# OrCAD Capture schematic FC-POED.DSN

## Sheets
1 INDEX: size A; title: INDEX; rev: 1.1; note: 8000100001
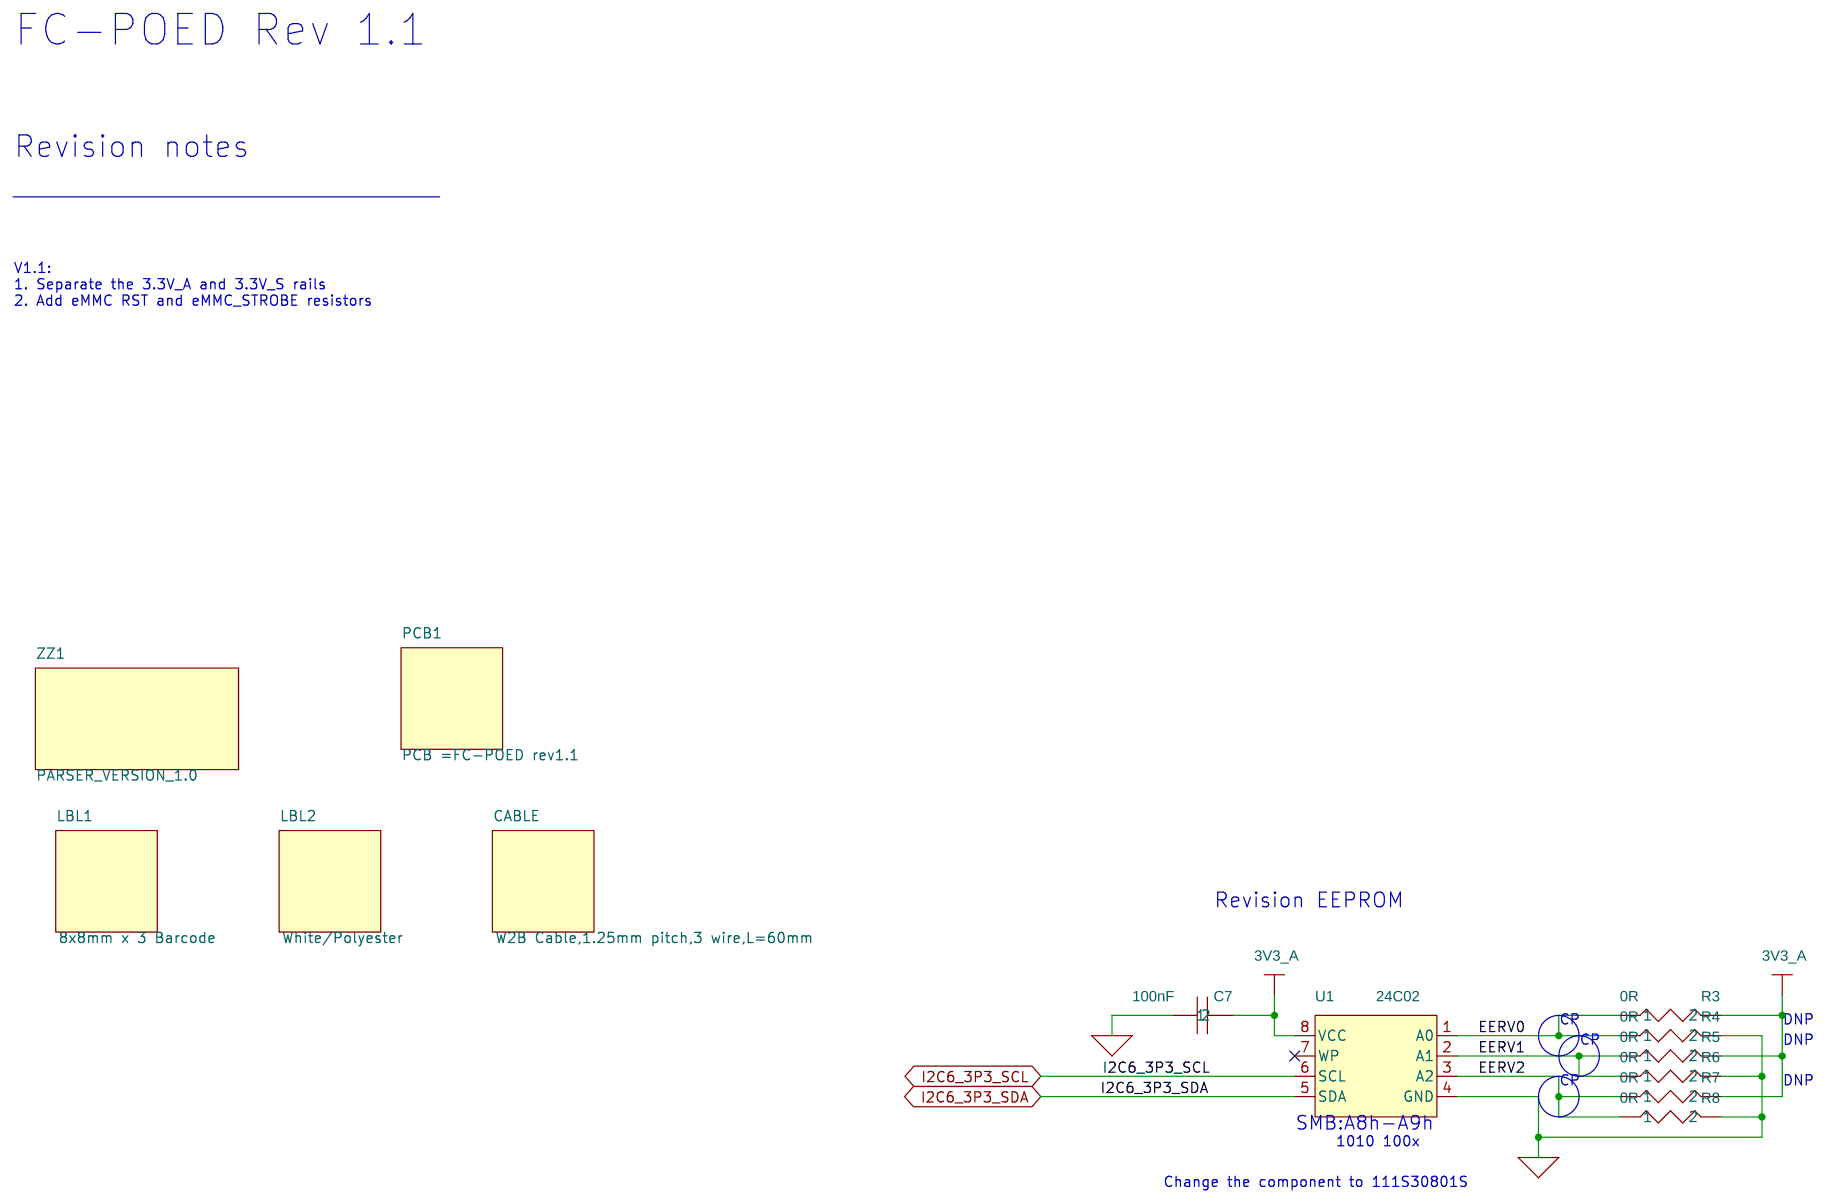
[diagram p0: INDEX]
2 M.2 WiFi: size Custom; title: M.2 interface
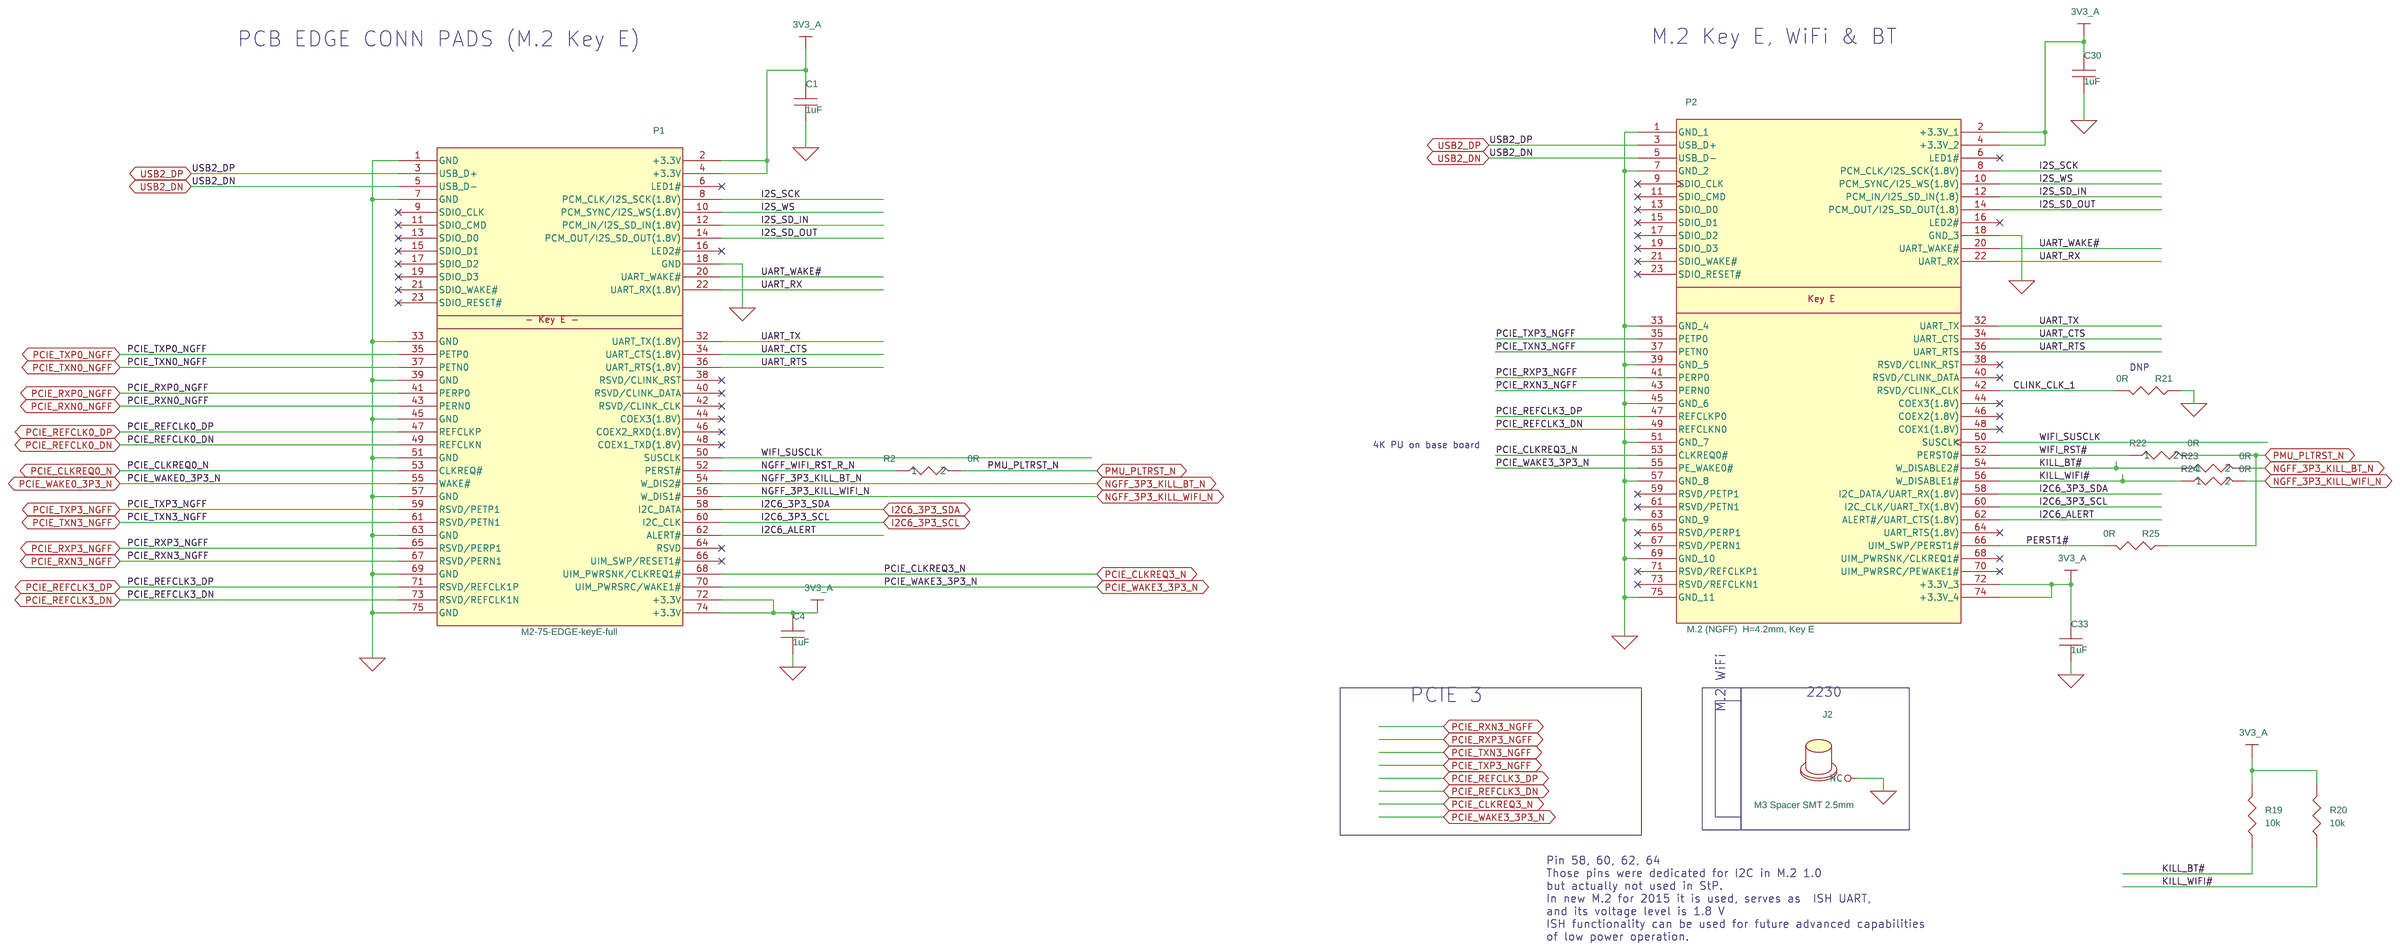
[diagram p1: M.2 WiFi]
3 1Gb LAN: size A3; title: GBE#0
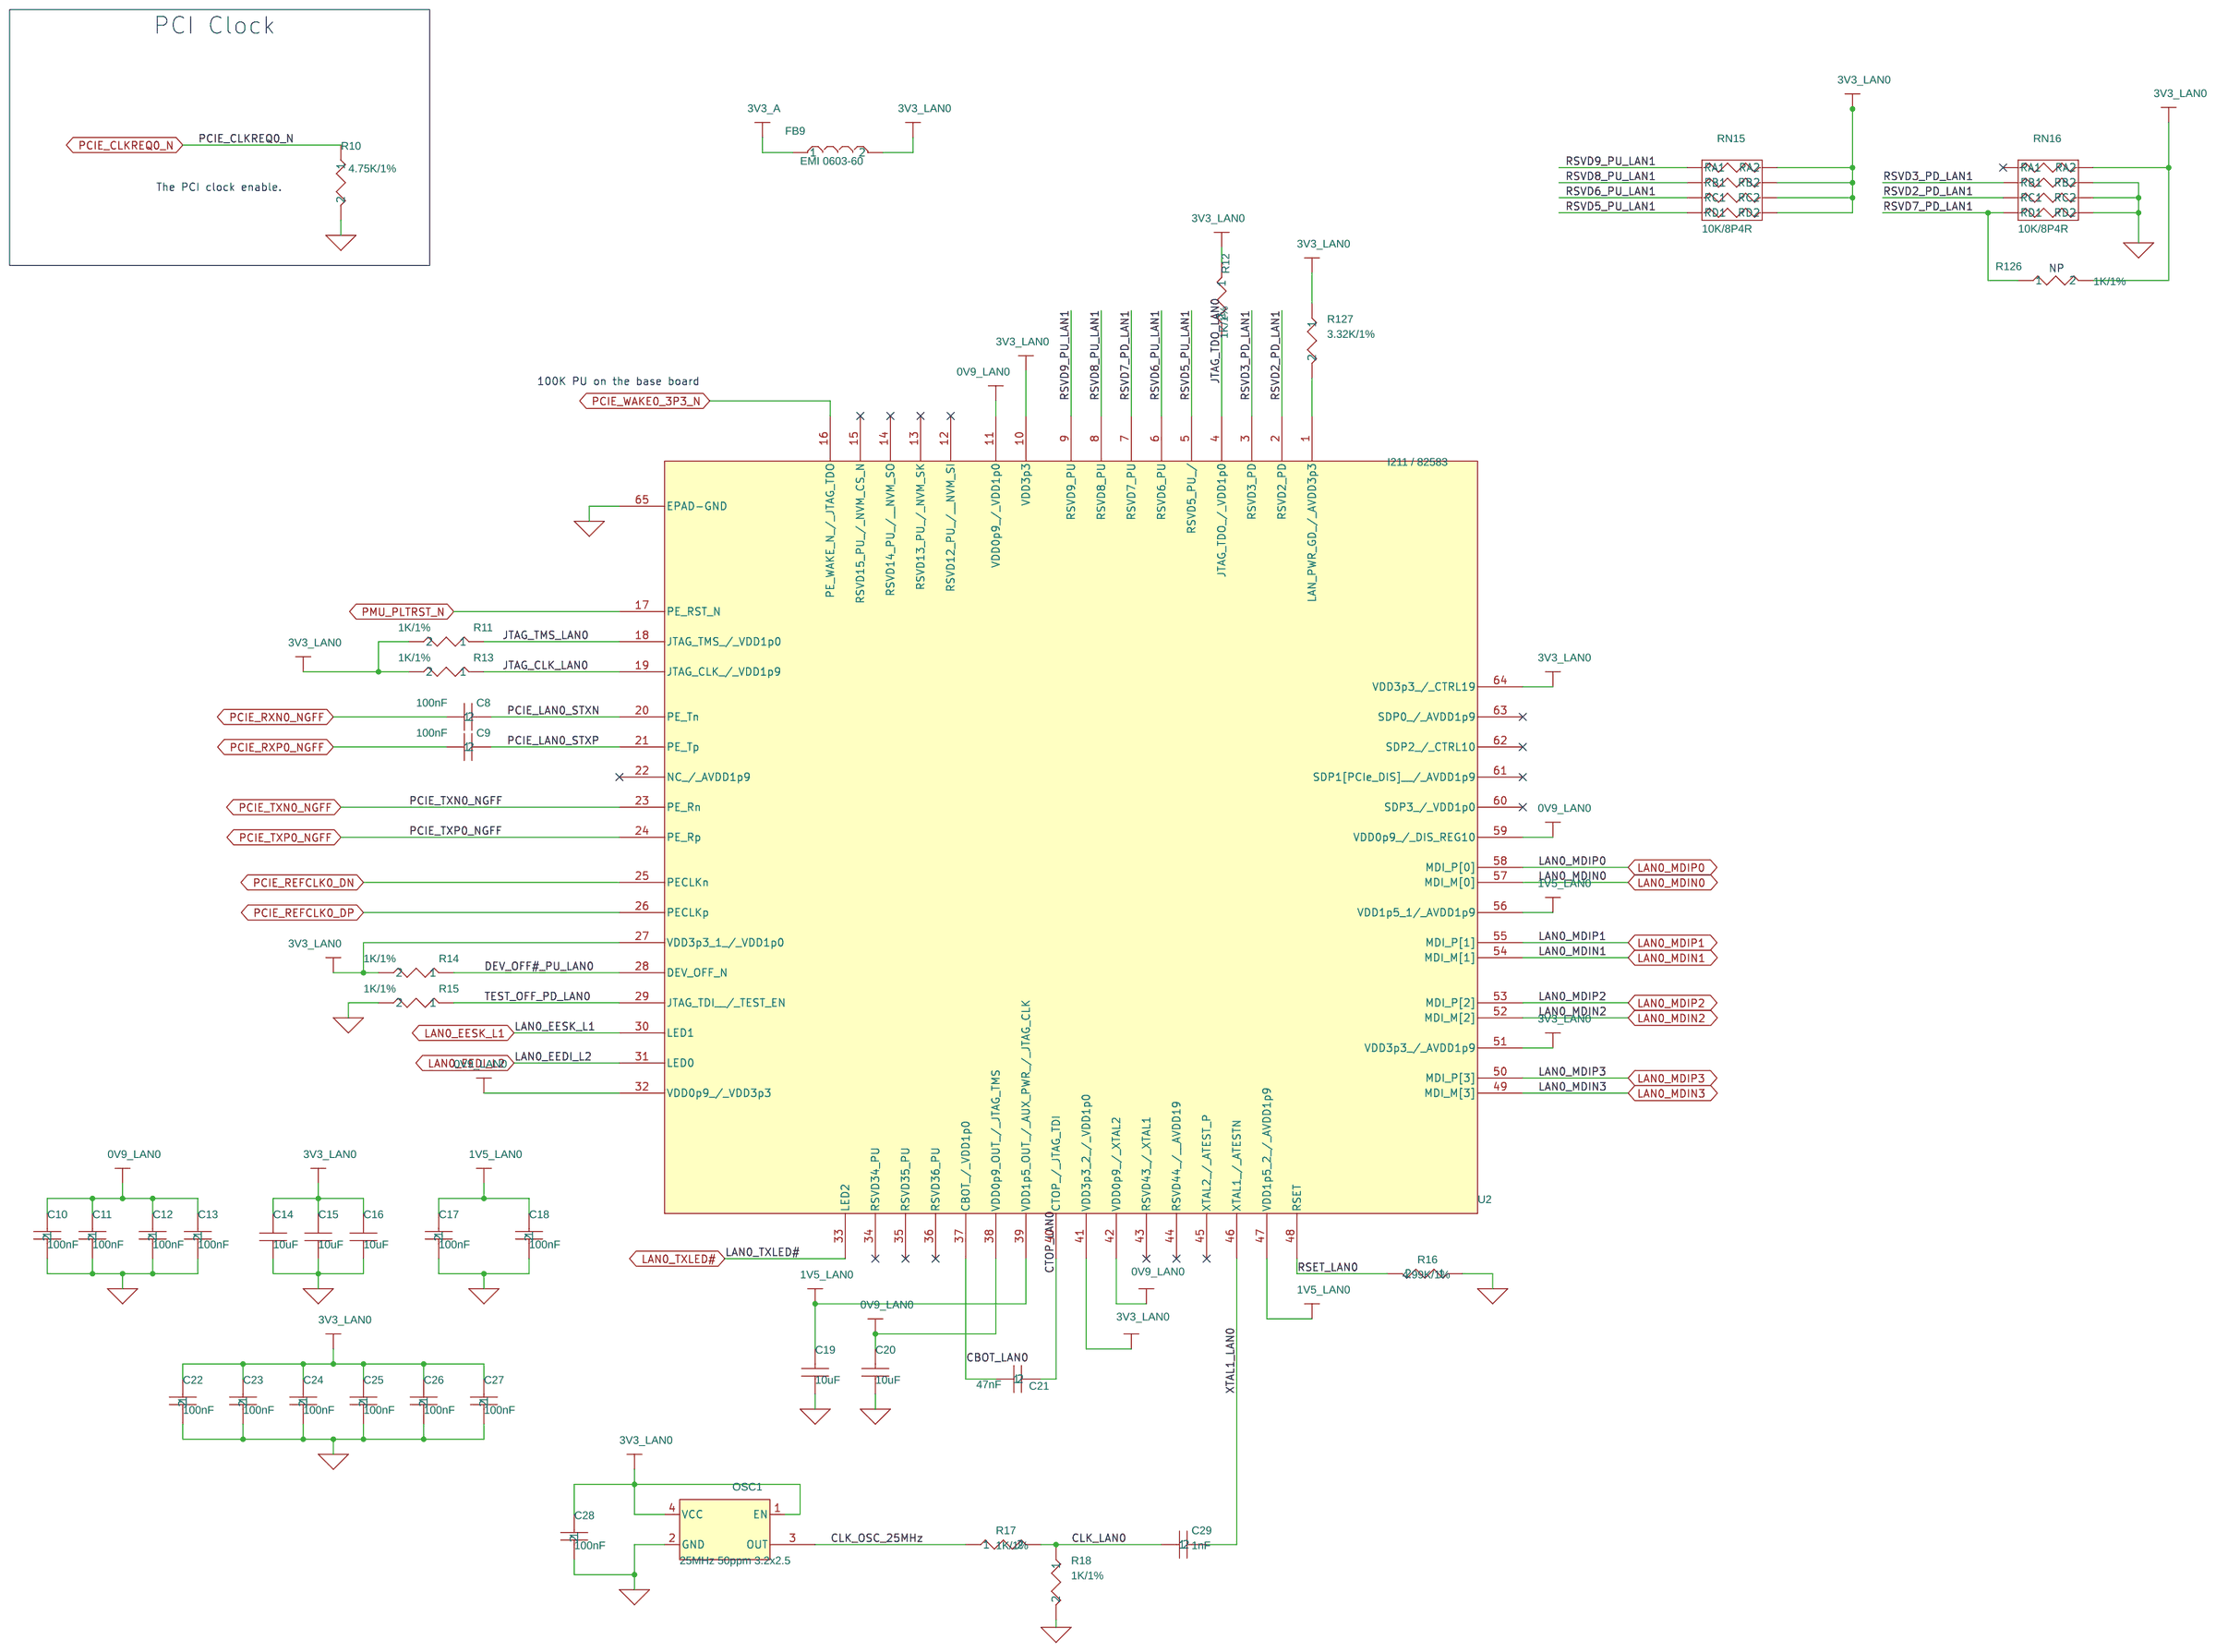
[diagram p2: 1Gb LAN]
4 POE: size C; title: POE
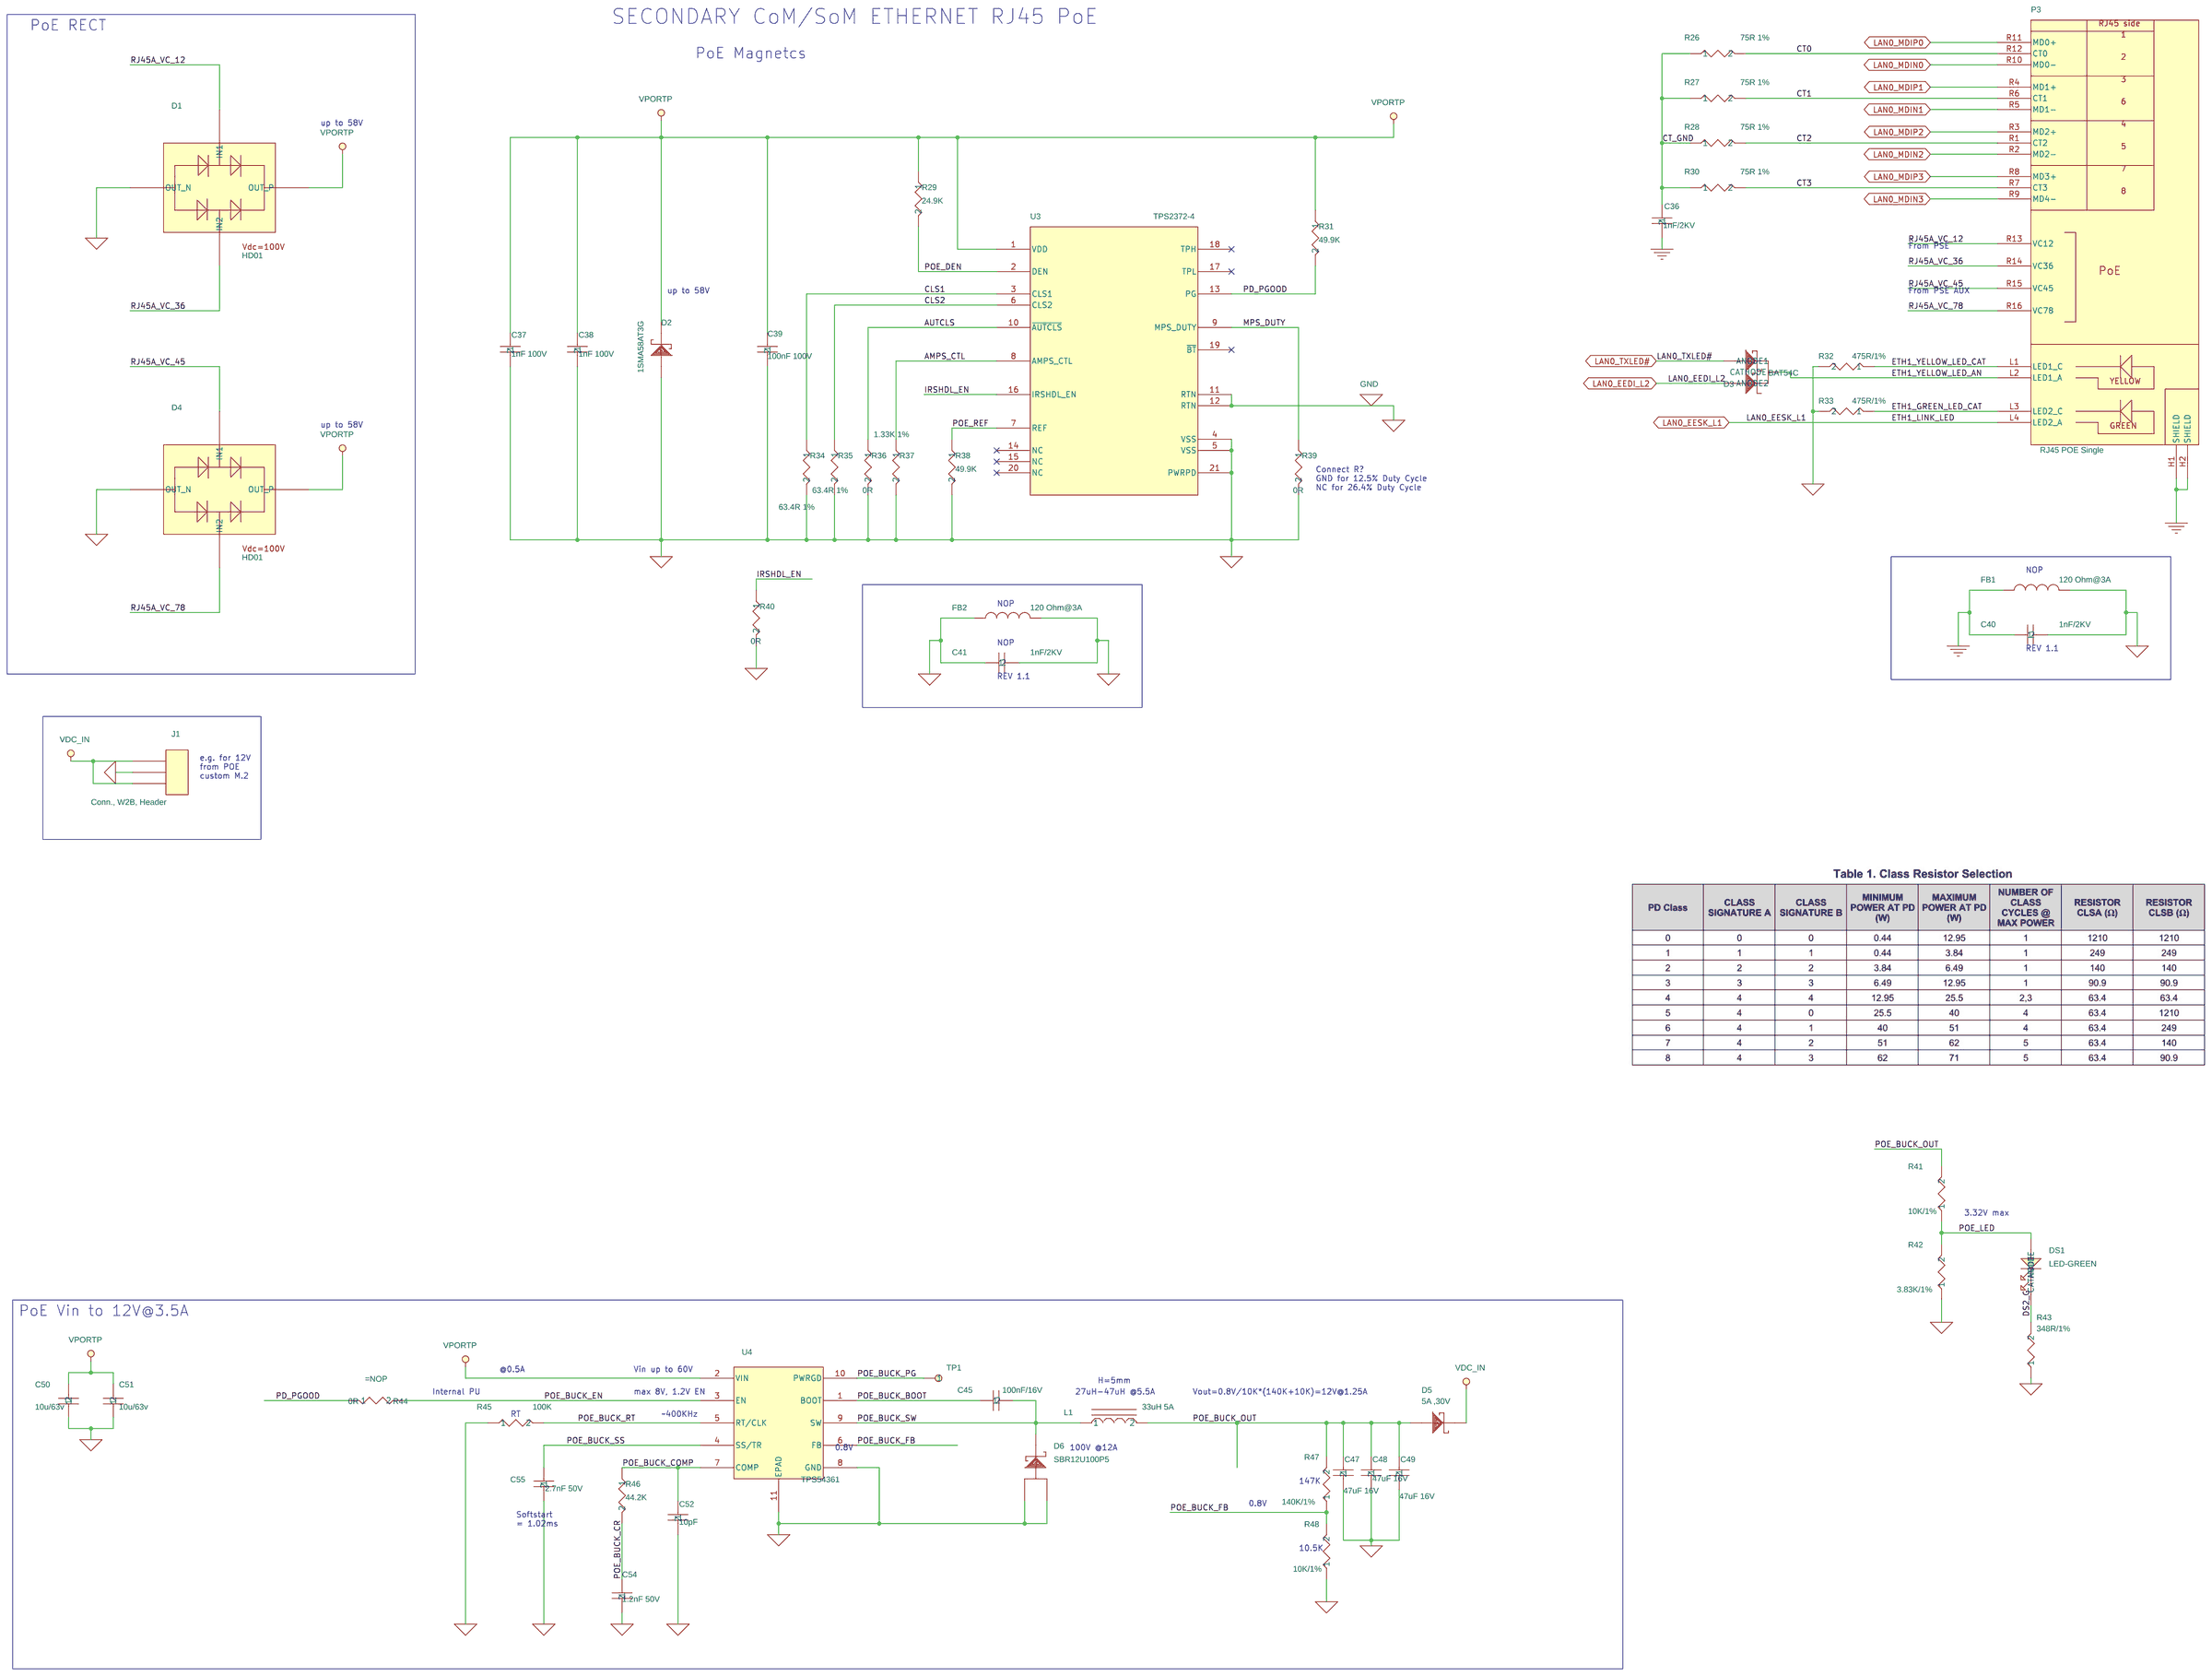
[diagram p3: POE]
5 M.2 SATA: size B; title: M.2 SATA
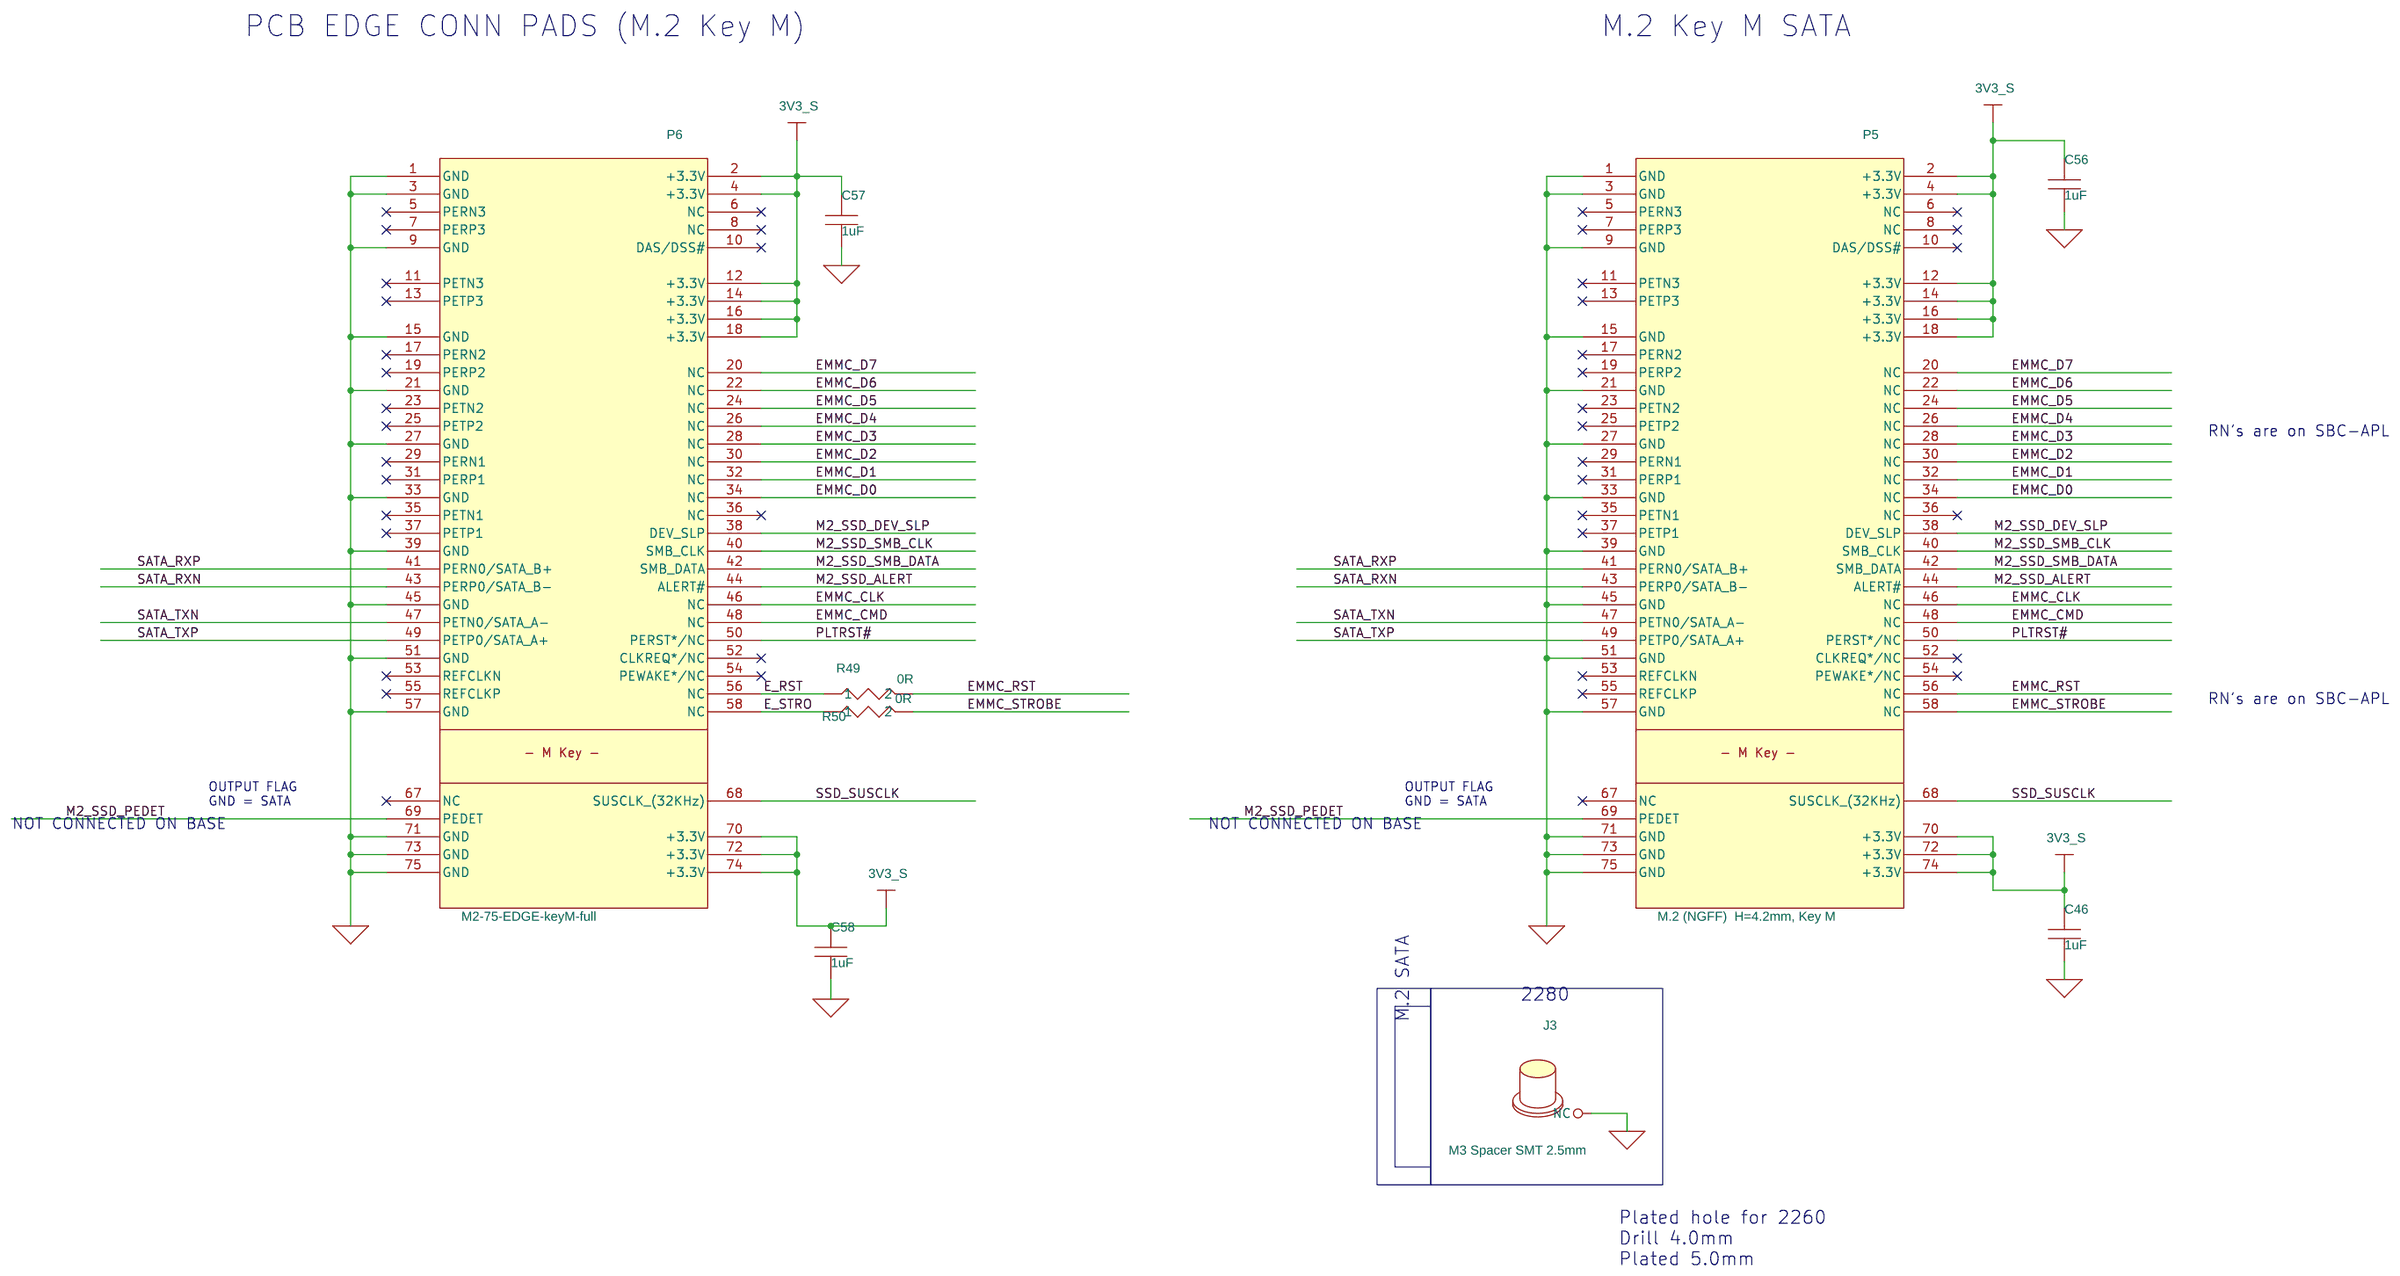
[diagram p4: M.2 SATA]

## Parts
sheet 1Gb LAN
C8  100nF  [RC0402]
C9  100nF  [RC0402]
C10  100nF  [RC0402]
C11  100nF  [RC0402]
C12  100nF  [RC0402]
C13  100nF  [RC0402]
C14  10uF  [RC0603]
C15  10uF  [RC0603]
C16  10uF  [RC0603]
C17  100nF  [RC0402]
C18  100nF  [RC0402]
C19  10uF  [RC0603]
C20  10uF  [RC0603]
C21  47nF  [RC0603]
C22  100nF  [RC0402]
C23  100nF  [RC0402]
C24  100nF  [RC0402]
C25  100nF  [RC0402]
C26  100nF  [RC0402]
C27  100nF  [RC0402]
C28  100nF  [RC0402]
C29  1nF  [RC0402]
FB9  EMI 0603-60  [FB0603]
OSC1  25MHz 50ppm 3.2x2.5  [OSC3225]
R10  4.75K/1%  [RC0402]
R11  1K/1%  [RC0402]
R12  1K/1%  [RC0402]
R13  1K/1%  [RC0402]
R14  1K/1%  [RC0402]
R15  1K/1%  [RC0402]
R16  4.99K/1%  [RC0402]
R17  1K/1%  [RC0402]
R18  1K/1%  [RC0402]
R126  1K/1%  [RC0402]
R127  3.32K/1%  [RC0402]
RN15  10K/8P4R  [RESNET8P0805]
RN16  10K/8P4R  [RESNET8P0805]
U2  I211 / 82583
sheet INDEX
C7  100nF  [RC0402]
CABLE  W2B Cable,1.25mm pitch,3 wire,L=60mm  [LBL]
LBL1  8x8mm x 3 Barcode  [LBL XYU]
LBL2  White/Polyester  [LBL]
PCB1  PCB =FC-POED rev1.1  [PCB]
R3  0R  [RC0402]
R4  0R  [RC0402]
R5  0R  [RC0402]
R6  0R  [RC0402]
R7  0R  [RC0402]
R8  0R  [RC0402]
U1  24C02  [MO-229VCED-2]
ZZ1  PARSER_VERSION_1.0
sheet M.2 SATA
C46  1uF  [RC0402]
C56  1uF  [RC0402]
C57  1uF  [RC0402]
C58  1uF  [RC0402]
J3  M3 Spacer SMT 2.5mm  [SpacerM3TAPSM]
P5  M.2 (NGFF)  H=4.2mm, Key M  [NGFF67P4HMkeySM]
P6  M2-75-EDGE-keyM-full  [EdgeM2keyM]
R49  0R  [RC0402]
R50  0R  [RC0402]
sheet M.2 WiFi
C1  1uF  [RC0402]
C4  1uF  [RC0402]
C30  1uF  [RC0402]
C33  1uF  [RC0402]
J2  M3 Spacer SMT 2.5mm  [SpacerM3TAPSM]
P1  M2-75-EDGE-keyE-full
P2  M.2 (NGFF)  H=4.2mm, Key E  [NGFF67P4HEkeySM]
R2  0R  [RC0402]
R19  10k  [RC0402]
R20  10k  [RC0402]
R21  0R  [RC0402]
R22  0R  [RC0402]
R23  0R  [RC0402]
R24  0R  [RC0402]
R25  0R  [RC0402]
sheet POE
C36  1nF/2KV  [C1812]
C37  1nF 100V
C38  1nF 100V
C39  100nF 100V  [1210]
C40  1nF/2KV  [C1812]
C41  1nF/2KV  [C1812]
C45  100nF/16V  [RC0603]
C47  47uF 16V  [1210]
C48  47uF 16V  [1210]
C49  47uF 16V  [1210]
C50  10u/63v  [C1210H2_5]
C51  10u/63v  [C1210H2_5]
C52  10pF  [RC0603]
C54  1.2nF 50V  [0402]
C55  2.7nF 50V  [0603]
D1  HD01  [TO-269AA]
D2  1SMA58AT3G  [DO-214AC]
D3  BAT54C  [SOT23]
D4  HD01  [TO-269AA]
D5  5A ,30V  [SOD-128]
D6  SBR12U100P5  [TO-277A]
DS1  LED-GREEN  [LED-1206]
FB1  120 Ohm@3A  [1206]
FB2  120 Ohm@3A  [1206]
J1  Conn., W2B, Header  [1x3W2B1_25RASM]
L1  33uH 5A  [IND13.5x12.5x5]
P3  RJ45 POE Single  [RJTR1GRATHPOE]
R26  75R 1%  [0402]
R27  75R 1%  [0402]
R28  75R 1%  [0402]
R29  24.9K  [0402]
R30  75R 1%  [0402]
R31  49.9K  [0402]
R32  475R/1%  [RC0402]
R33  475R/1%  [RC0402]
R34  63.4R 1%  [0402]
R35  63.4R 1%  [0402]
R36  0R  [RC0402]
R37  1.33K 1%  [0402]
R38  49.9K  [0402]
R39  0R  [RC0402]
R40  0R  [RC0402]
R41  10K/1%  [RC0402]
R42  3.83K/1%  [RC0402]
R43  348R/1%  [RC0402]
R44  0R  [RC0402]
R45  100K  [RC0402]
R46  44.2K  [0402]
R47  140K/1%  [RC0402]
R48  10K/1%  [RC0402]
TP1  TESTPOINT  [TESTPOINT]
U3  TPS2372-4  [VQFN (20)]
U4  TPS54361  [DFN4x4-10]

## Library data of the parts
C8 = 100nF,_10V,_X7R,_10%,_0402_8: CLABCONF0: =FC-POED; Group: LAN2
C9 = 100nF,_10V,_X7R,_10%,_0402_5: CLABCONF0: =FC-POED; Group: LAN2
C10 = 100nF,_10V,_X7R,_10%,_0402_11: CLABCONF0: =FC-POED
C11 = 100nF,_10V,_X7R,_10%,_0402_14: CLABCONF0: =FC-POED
C12 = 100nF,_10V,_X7R,_10%,_0402_10: CLABCONF0: =FC-POED
C13 = 100nF,_10V,_X7R,_10%,_0402_13: CLABCONF0: =FC-POED
C14 = 10uF,6.3V,0603,X5R_1: CLABCONF0: =FC-POED
C15 = 10uF,6.3V,0603,X5R: CLABCONF0: =FC-POED
C16 = 10uF,6.3V,0603,X5R_2: CLABCONF0: =FC-POED
C7 C17 = 100nF,_10V,_X7R,_10%,_0402: CLABCONF0: =FC-POED
C18 = 100nF,_10V,_X7R,_10%,_0402_4: CLABCONF0: =FC-POED
C19 = 10uF,6.3V,0603,X5R_3: CLABCONF0: =FC-POED
C20 = 10uF,6.3V,0603,X5R_4: CLABCONF0: =FC-POED
C21 = 47nF,_25V,_X7R,_10%,_0603: CLABCONF0: =FC-POED
C22 = 100nF,_10V,_X7R,_10%,_0402_7: CLABCONF0: =FC-POED
C23 = 100nF,_10V,_X7R,_10%,_0402_9: CLABCONF0: =FC-POED
C24 = 100nF,_10V,_X7R,_10%,_0402_6: CLABCONF0: =FC-POED
C25 = 100nF,_10V,_X7R,_10%,_0402_12: CLABCONF0: =FC-POED
C26 = 100nF,_10V,_X7R,_10%,_0402_3: CLABCONF0: =FC-POED
C27 = 100nF,_10V,_X7R,_10%,_0402_1: CLABCONF0: =FC-POED
C28 = 100nF,_10V,_X7R,_10%,_0402_2: CLABCONF0: =FC-POED; Group: LAN2
C29 = 1nF,10%,_50V,_X7R,_0402: CLABCONF0: =FC-POED
FB9 = Ferrit_60R@100Mhz_0.4A_0.3R_DCR: CLABCONF0: =FC-POED
OSC1 = 25MHz,50PPM,OSC3225,_3.3V: CLABCONF0: =FC-POED
R10 = 4.75K,1%,0402,1_16W: CLABCONF0: =FC-POED
R11 = 1K,1%,0402,1_16W_6: CLABCONF0: =FC-POED
R12 = 1K,1%,0402,1_16W_7: CLABCONF0: =FC-POED
R13 = 1K,1%,0402,1_16W_1: CLABCONF0: =FC-POED
R14 = 1K,1%,0402,1_16W_4: CLABCONF0: =FC-POED
R15 = 1K,1%,0402,1_16W_5: CLABCONF0: =FC-POED
R16 = 4.99K,1%,0402,1_16W: CLABCONF0: =FC-POED
R17 = 1K,1%,0402,1_16W_2: CLABCONF0: =FC-POED
R18 = 1K,1%,0402,1_16W: CLABCONF0: =FC-POED
R126 = 1K,1%,0402,1_16W_3: CLABCONF0: =NOP
R127 = 3.32K,1%,0402,1_16W: CLABCONF0: =FC-POED
RN15 RN16 = RN,10K,8P4R@0805: CLABCONF0: =FC-POED
U2 = IC,_I211_,PCIE_1Gb_LAN_0: CLABCONF0: =FC-POED; P/N: 116B00070S
CABLE = Label_white_polyester: CLABCONF0: =NOP; P/N: 504B010030
LBL1 = Label_8x8mm_x_3_for_Barcode: CLABCONF0: =FC-POED
LBL2 = Label_white_polyester: CLABCONF0: =FC-POED; P/N: 374F13P20C
PCB1 = PCB_FC-LAN.rev1.0: CLABCONF0: =FC-POED; P/N: 188C03201
R3 = 0R,_0402_5: CLABCONF0: =FC-POED
R4 = 0R,_0402_3: CLABCONF0: =NOP
R5 = 0R,_0402_4: CLABCONF0: =NOP
R2 R6 R39 R50 = 0R,_0402_1: CLABCONF0: =FC-POED
R7 = 0R,_0402_2: CLABCONF0: =NOP
R8 R22 R40 R49 = 0R,_0402: CLABCONF0: =FC-POED
U1 = 24C02,_serial_EE,_2KB,_I2C_0: CLABCONF0: =FC-POED; P/N: 111S30800S
ZZ1 = PARSER_VERSION_1.0: CLABCONF0: =FC-POED
C1 C4 C30 C33 C46 C56-C58 = 1uF,X5R,6.3V,0402: CLABCONF0: =FC-POED
J2 J3 = Spacer_SMT,_M2,_4mm: CLABCONF0: =FC-POED; P/N: 383B54510S
P5 = Conn.,_M_0.2_Key_M_SATA_PCIex4: CLABCONF0: =FC-POED; P/N: 182K06700S
P6 = Conn.,_M_0.2_Key_M_SATA_PCIex4
P1 = M2-75-EDGE-_keyE-full_0
P2 = Conn.,_M.2_Key_E_PCIe: CLABCONF0: =FC-POED; P/N: 182K06701S
R19 R20 = 1M_,5%,_0402_0: CLABCONF0: =FC-POED; P/N: 161C10021S
R21 = 0R_0: CLABCONF0: =NOP
R23 = 0R,_0402_3: CLABCONF0: =FC-POED
R24 R36 = 0R,_0402_2: CLABCONF0: =FC-POED
R25 = 0R_0: CLABCONF0: =FC-POED
C36 = 1nF,_2KV,SMD_1812,_X7R,_10%: CLABCONF0: =FC-POED
C37 = 1nF_100V_X7R_10%_0603: CLABCONF0: =FC-POED
C38 = 1nF_100V_X7R_10%_0603_1: CLABCONF0: =FC-POED
C39 = 100nF_100V_20%,_1210: CLABCONF0: =FC-POED
C40 = 1nF,_2KV,SMD_1812,_X7R,_10%_1: CLABCONF0: =FC-POED
C41 = 1nF,_2KV,SMD_1812,_X7R,_10%_2: CLABCONF0: =NOP
C45 = 100nF_0603_0: CLABCONF0: =FC-POED; P/N: 151K10410S
C47 = 47uF_16V_X5R_20%_1210_H=2.5mm_2: CLABCONF0: =FC-POED
C48 = 47uF_16V_X5R_20%_1210_H=2.5mm: CLABCONF0: =FC-POED
C49 = 47uF_16V_X5R_20%_1210_H=2.5mm_1: CLABCONF0: =FC-POED
C50 = 100nF,_10V,_X7R,_10%,_0402: CLABCONF0: =FC-POED; P/N: 151E10680S
C51 = 100nF,_10V,_X7R,_10%,_0402_1: CLABCONF0: =FC-POED; P/N: 151E10680S
C52 = 10pF,50V,NPO,0603: CLABCONF0: =FC-POED
C54 = 1.2nF_50V_0402_X7R_10%: CLABCONF0: =FC-POED
C55 = 2.7nF_50V_NPO_0603_5%: CLABCONF0: =FC-POED
D1 D4 = HD01_1: CLABCONF0: =FC-POED; P/N: 130D30800S
D2 = Diode_,MBRS340_,3A_0: CLABCONF0: =FC-POED; P/N: 132D10060S
D3 = BAT54C: CLABCONF0: =FC-POED
D5 = Diode_Shotky,5A,30V: CLABCONF0: =FC-POED
D6 = Diode_,SBR12U100P5: CLABCONF0: =FC-POED; P/N: 130E12000S
DS1 = LED-GREEN_1206: CLABCONF0: =FC-POED; Group: Always
FB1 = Ferrite_bead_,_120_Ohm@3A_1: CLABCONF0: =NOP
FB2 = Ferrite_bead_,_120_Ohm@3A: CLABCONF0: =NOP
J1 = CON3: CLABCONF0: =FC-POED; P/N: 182E00302S
L1 = 33uH_Irms=_5A_Isat=_8A_Shielded: CLABCONF0: =FC-POED
P3 = RJ45_POE_Single_1: CLABCONF0: =FC-POED; P/N: 182K02003
R26 = 75R_1%_0402_1_16W_2: CLABCONF0: =FC-POED
R27 = 75R_1%_0402_1_16W_3: CLABCONF0: =FC-POED
R28 = 75R_1%_0402_1_16W: CLABCONF0: =FC-POED
R29 = 24.9K_1%_0402_1_16W: CLABCONF0: =FC-POED
R30 = 75R_1%_0402_1_16W_1: CLABCONF0: =FC-POED
R31 = 49.9K_1%_0402_1_16W_1: CLABCONF0: =FC-POED
R32 = 475R_1%,_0402: CLABCONF0: =FC-POED
R33 = 475R_1%,_0402_1: CLABCONF0: =FC-POED
R34 = 63.4R_1%_0402_1_16W_1: CLABCONF0: =FC-POED
R35 = 63.4R_1%_0402_1_16W: CLABCONF0: =FC-POED
R37 = 1.33K_1%_0402_1_16W: CLABCONF0: =FC-POED
R38 = 49.9K_1%_0402_1_16W: CLABCONF0: =FC-POED
R41 = 10K,1%,0402,1_16W_2: CLABCONF0: =FC-POED
R42 = 4.99K,1%,0402,1_16W: CLABCONF0: =FC-POED; P/N: 161C38311S
R43 = 348R,1%,0402,1_16W: CLABCONF0: =FC-POED
R44 = 0R,_0402_0: CLABCONF0: =NOP
R45 = 100K,_0402_0: CLABCONF0: =FC-POED
R46 = 44.2K_1%_0402: CLABCONF0: =FC-POED
R47 = 10K,1%,0402,1_16W: CLABCONF0: =FC-POED; P/N: 161C14031S
R48 = 10K,1%,0402,1_16W_1: CLABCONF0: =FC-POED
TP1 = TESTPOINT: CLABCONF0: =FC-POED
U3 = TPS2372-4_3: CLABCONF0: =FC-POED
U4 = TPS54361_0: CLABCONF0: =FC-POED; P/N: 123V58R80S

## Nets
0V9_LAN0: C10.1 C11.1 C12.1 C13.1 C20.2 U2.11(VDD0p9_/_VDD1p0) U2.32(VDD0p9_/_VDD3p3) U2.38(VDD0p9_OUT_/_JTAG_TMS) U2.42(VDD0p9_/_XTAL2) U2.59(VDD0p9_/_DIS_REG10)
1V5_LAN0: C17.1 C18.1 C19.2 U2.39(VDD1p5_OUT_/_AUX_PWR_/_JTAG_CLK) U2.47(VDD1p5_2_/_AVDD1p9) U2.56(VDD1p5_1/_AVDD1p9)
3V3_A: C1.1 C4.1 C7.2 C30.1 C33.1 FB9.1 P1.2(+3.3V) P1.4(+3.3V) P1.72(+3.3V) P1.74(+3.3V) P2.2(+3.3V_1) P2.4(+3.3V_2) P2.72(+3.3V_3) P2.74(+3.3V_4) R3.2 R5.2 R7.2 R19.2 R20.2 U1.8(VCC)
3V3_LAN0: C14.2 C15.2 C16.2 C22.1 C23.1 C24.1 C25.1 C26.1 C27.1 C28.1 FB9.2 OSC1.1(EN) OSC1.4(VCC) R11.2 R12.1 R13.2 R14.2 R126.2 R127.1 RN15.5(RD2) RN15.6(RC2) RN15.7(RB2) RN15.8(RA2) RN16.8(RA2) U2.10(VDD3p3) U2.27(VDD3p3_1_/_VDD1p0) U2.41(VDD3p3_2_/_VDD1p0) U2.51(VDD3p3_/_AVDD1p9) U2.64(VDD3p3_/_CTRL19)
3V3_S: C46.1 C56.1 C57.1 C58.1 P5.2(+3.3V) P5.4(+3.3V) P5.12(+3.3V) P5.14(+3.3V) P5.16(+3.3V) P5.18(+3.3V) P5.70(+3.3V) P5.72(+3.3V) P5.74(+3.3V) P6.2(+3.3V) P6.4(+3.3V) P6.12(+3.3V) P6.14(+3.3V) P6.16(+3.3V) P6.18(+3.3V) P6.70(+3.3V) P6.72(+3.3V) P6.74(+3.3V)
GND: C1.2 C4.2 C7.1 C10.2 C11.2 C12.2 C13.2 C14.1 C15.1 C16.1 C17.2 C18.2 C19.1 C20.1 C22.2 C23.2 C24.2 C25.2 C26.2 C27.2 C28.2 C30.2 C33.2 C40.2 C41.2 C46.2 C47.2 C48.2 C49.2 C50.1 C51.1 C52.2 C54.2 C55.2 C56.2 C57.2 C58.2 D6.1(ANODE1) D6.2(ANODE2) FB1.2 FB2.2 J1.2 J2.NC J3.NC OSC1.2(GND) P1.1(GND) P1.7(GND) P1.18(GND) P1.33(GND) P1.39(GND) P1.45(GND) P1.51(GND) P1.57(GND) P1.63(GND) P1.69(GND) P1.75(GND) P2.1(GND) P2.7(GND_2) P2.18(GND_3) P2.33(GND_4) P2.39(GND_5) P2.45(GND_6) P2.51(GND_7) P2.57(GND_8) P2.63(GND_9) P2.69(GND_10) P2.75(GND_11) P5.1(GND) P5.3(GND) P5.9(GND) P5.15(GND) P5.21(GND) P5.27(GND) P5.33(GND) P5.39(GND) P5.45(GND) P5.51(GND) P5.57(GND) P5.71(GND) P5.73(GND) P5.75(GND) P6.1(GND) P6.3(GND) P6.9(GND) P6.15(GND) P6.21(GND) P6.27(GND) P6.33(GND) P6.39(GND) P6.45(GND) P6.51(GND) P6.57(GND) P6.71(GND) P6.73(GND) P6.75(GND) R4.2 R6.2 R8.2 R10.2 R15.2 R16.1 R18.2 R21.1 R32.2 R33.2 R40.2 R42.1 R43.1 R45.1 R48.1 RN16.5(RD2) RN16.6(RC2) RN16.7(RB2) U1.4(GND) U2.65(EPAD-GND) U3.11(RTN) U3.12(RTN) U4.8(GND) U4.11(EPAD)
AMPS_CTL: R37.1 U3.8(AMPS_CTL)
AUTCLS: R36.1 U3.10(~{AUTCLS})
CBOT_LAN0: C21.1 U2.37(CBOT_/_VDD1p0)
CLINK_CLK_1: P2.42(RSVD/CLINK_CLK) R21.2
CLK_LAN0: C29.1 R17.2 R18.1
CLK_OSC_25MHz: OSC1.3(OUT) R17.1
CLS1: R34.1 U3.3(CLS1)
CLS2: R35.1 U3.6(CLS2)
CT0: P3.R12(CT0) R26.2
CT1: P3.R6(CT1) R27.2
CT2: P3.R1(CT2) R28.2
CT3: P3.R7(CT3) R30.2
CT_GND: C36.1 R26.1 R27.1 R28.1 R30.1
CTOP_LAN0: C21.2 U2.40(CTOP_/_JTAG_TDI)
DEV_OFF#_PU_LAN0: R14.1 U2.28(DEV_OFF_N)
DS2_G: DS1.CATHODE R43.2
E_RST: P6.56(NC) R49.1
E_STRO: P6.58(NC) R50.1
EERV0: R3.1 R4.1 U1.1(A0)
EERV1: R5.1 R6.1 U1.2(A1)
EERV2: R7.1 R8.1 U1.3(A2)
EMMC_CLK: P5.46(NC) P6.46(NC)
EMMC_CMD: P5.48(NC) P6.48(NC)
EMMC_D0: P5.34(NC) P6.34(NC)
EMMC_D1: P5.32(NC) P6.32(NC)
EMMC_D2: P5.30(NC) P6.30(NC)
EMMC_D3: P5.28(NC) P6.28(NC)
EMMC_D4: P5.26(NC) P6.26(NC)
EMMC_D5: P5.24(NC) P6.24(NC)
EMMC_D6: P5.22(NC) P6.22(NC)
EMMC_D7: P5.20(NC) P6.20(NC)
EMMC_RST: P5.56(NC) R49.2
EMMC_STROBE: P5.58(NC) R50.2
ETH1_GREEN_LED_CAT: P3.L3(LED2_C) R33.1
ETH1_YELLOW_LED_AN: D3.3(CATHODE) P3.L2(LED1_A)
ETH1_YELLOW_LED_CAT: P3.L1(LED1_C) R32.1
I2C6_3P3_SCL: P1.60(I2C_CLK) P2.60(I2C_CLK/UART_TX(1.8V)) U1.6(SCL)
I2C6_3P3_SDA: P1.58(I2C_DATA) P2.58(I2C_DATA/UART_RX(1.8V)) U1.5(SDA)
I2C6_ALERT: P1.62(ALERT#) P2.62(ALERT#/UART_CTS(1.8V))
I2S_SCK: P1.8(PCM_CLK/I2S_SCK(1.8V)) P2.8(PCM_CLK/I2S_SCK(1.8V))
I2S_SD_IN: P1.12(PCM_IN/I2S_SD_IN(1.8V)) P2.12(PCM_IN/I2S_SD_IN(1.8))
I2S_SD_OUT: P1.14(PCM_OUT/I2S_SD_OUT(1.8V)) P2.14(PCM_OUT/I2S_SD_OUT(1.8))
I2S_WS: P1.10(PCM_SYNC/I2S_WS(1.8V)) P2.10(PCM_SYNC/I2S_WS(1.8V))
IRSHDL_EN: R40.1 U3.16(IRSHDL_EN)
JTAG_CLK_LAN0: R13.1 U2.19(JTAG_CLK_/_VDD1p9)
JTAG_TDO_LAN0: R12.2 U2.4(JTAG_TDO_/_VDD1p0)
JTAG_TMS_LAN0: R11.1 U2.18(JTAG_TMS_/_VDD1p0)
KILL_BT#: P2.54(W_DISABLE2#) R19.1 R23.1
KILL_WIFI#: P2.56(W_DISABLE1#) R20.1 R24.1
LAN0_EEDI_L2: D3.2(ANODE2) U2.31(LED0)
LAN0_EESK_L1: P3.L4(LED2_A) U2.30(LED1)
LAN0_MDIN0: P3.R10(MD0-) U2.57(MDI_M[0])
LAN0_MDIN1: P3.R5(MD1-) U2.54(MDI_M[1])
LAN0_MDIN2: P3.R2(MD2-) U2.52(MDI_M[2])
LAN0_MDIN3: P3.R9(MD4-) U2.49(MDI_M[3])
LAN0_MDIP0: P3.R11(MD0+) U2.58(MDI_P[0])
LAN0_MDIP1: P3.R4(MD1+) U2.55(MDI_P[1])
LAN0_MDIP2: P3.R3(MD2+) U2.53(MDI_P[2])
LAN0_MDIP3: P3.R8(MD3+) U2.50(MDI_P[3])
LAN0_TXLED#: D3.1(ANODE1) U2.33(LED2)
M2_SSD_ALERT: P5.44(ALERT#) P6.44(ALERT#)
M2_SSD_DEV_SLP: P5.38(DEV_SLP) P6.38(DEV_SLP)
M2_SSD_PEDET: P5.69(PEDET) P6.69(PEDET)
M2_SSD_SMB_CLK: P5.40(SMB_CLK) P6.40(SMB_CLK)
M2_SSD_SMB_DATA: P5.42(SMB_DATA) P6.42(SMB_DATA)
MPS_DUTY: R39.1 U3.9(MPS_DUTY)
NGFF_3P3_KILL_BT_N: P1.54(W_DIS2#) R23.2
NGFF_3P3_KILL_WIFI_N: P1.56(W_DIS1#) R24.2
NGFF_WIFI_RST_R_N: P1.52(PERST#) R2.1
PCIE_CLKREQ0_N: P1.53(CLKREQ#) R10.1
PCIE_CLKREQ3_N: P1.68(UIM_PWRSNK/CLKREQ1#) P2.53(CLKREQ0#)
PCIE_LAN0_STXN: C8.2 U2.20(PE_Tn)
PCIE_LAN0_STXP: C9.2 U2.21(PE_Tp)
PCIE_REFCLK0_DN: P1.49(REFCLKN) U2.25(PECLKn)
PCIE_REFCLK0_DP: P1.47(REFCLKP) U2.26(PECLKp)
PCIE_REFCLK3_DN: P1.73(RSVD/REFCLK1N) P2.49(REFCLKN0)
PCIE_REFCLK3_DP: P1.71(RSVD/REFCLK1P) P2.47(REFCLKP0)
PCIE_RXN0_NGFF: C8.1 P1.43(PERN0)
PCIE_RXN3_NGFF: P1.67(RSVD/PERN1) P2.43(PERN0)
PCIE_RXP0_NGFF: C9.1 P1.41(PERP0)
PCIE_RXP3_NGFF: P1.65(RSVD/PERP1) P2.41(PERP0)
PCIE_TXN0_NGFF: P1.37(PETN0) U2.23(PE_Rn)
PCIE_TXN3_NGFF: P1.61(RSVD/PETN1) P2.37(PETN0)
PCIE_TXP0_NGFF: P1.35(PETP0) U2.24(PE_Rp)
PCIE_TXP3_NGFF: P1.59(RSVD/PETP1) P2.35(PETP0)
PCIE_WAKE0_3P3_N: P1.55(WAKE#) U2.16(PE_WAKE_N_/_JTAG_TDO)
PCIE_WAKE3_3P3_N: P1.70(UIM_PWRSRC/WAKE1#) P2.55(PE_WAKE0#)
PD_PGOOD: R31.2 R44.1 U3.13(PG)
PERST1#: P2.66(UIM_SWP/PERST1#) R25.2
PLTRST#: P5.50(PERST*/NC) P6.50(PERST*/NC)
PMU_PLTRST_N: R2.2 R22.2 R25.1 U2.17(PE_RST_N)
POE_BUCK_BOOT: C45.1 U4.1(BOOT)
POE_BUCK_COMP: C52.1 R46.1 U4.7(COMP)
POE_BUCK_CR: C54.1 R46.2
POE_BUCK_EN: R44.2 U4.3(EN)
POE_BUCK_FB: R47.1 R48.2 U4.6(FB)
POE_BUCK_OUT: C47.1 C48.1 C49.1 D5.ANODE L1.2 R41.2 R47.2
POE_BUCK_PG: TP1.1 U4.10(PWRGD)
POE_BUCK_RT: R45.2 U4.5(RT/CLK)
POE_BUCK_SS: C55.1 U4.4(SS/TR)
POE_BUCK_SW: C45.2 D6.3(CATHODE) L1.1 U4.9(SW)
POE_DEN: R29.2 U3.2(DEN)
POE_LED: DS1.ANODE R41.1 R42.2
POE_REF: R38.1 U3.7(REF)
POE_RTN: C37.2 C38.2 C39.2 C41.1 D1.1(OUT_N) D2.ANODE D4.1(OUT_N) FB2.1 R34.2 R35.2 R36.2 R37.2 R38.2 R39.2 U3.4(VSS) U3.5(VSS) U3.21(PWRPD)
PoE_SHIELD: C36.2 C40.1 FB1.1 P3.H1(SHIELD) P3.H2(SHIELD)
RJ45A_VC_12: D1.3(IN1) P3.R13(VC12)
RJ45A_VC_36: D1.4(IN2) P3.R14(VC36)
RJ45A_VC_45: D4.3(IN1) P3.R15(VC45)
RJ45A_VC_78: D4.4(IN2) P3.R16(VC78)
RSET_LAN0: R16.2 U2.48(RSET)
RSVD2_PD_LAN1: RN16.3(RC1) U2.2(RSVD2_PD)
RSVD3_PD_LAN1: RN16.2(RB1) U2.3(RSVD3_PD)
RSVD5_PU_LAN1: RN15.4(RD1) U2.5(RSVD5_PU_/)
RSVD6_PU_LAN1: RN15.3(RC1) U2.6(RSVD6_PU)
RSVD7_PD_LAN1: R126.1 RN16.4(RD1) U2.7(RSVD7_PU)
RSVD8_PU_LAN1: RN15.2(RB1) U2.8(RSVD8_PU)
RSVD9_PU_LAN1: RN15.1(RA1) U2.9(RSVD9_PU)
SATA_RXN: P5.43(PERP0/SATA_B-) P6.43(PERP0/SATA_B-)
SATA_RXP: P5.41(PERN0/SATA_B+) P6.41(PERN0/SATA_B+)
SATA_TXN: P5.47(PETN0/SATA_A-) P6.47(PETN0/SATA_A-)
SATA_TXP: P5.49(PETP0/SATA_A+) P6.49(PETP0/SATA_A+)
SSD_SUSCLK: P5.68(SUSCLK_(32KHz)) P6.68(SUSCLK_(32KHz))
TEST_OFF_PD_LAN0: R15.1 U2.29(JTAG_TDI__/_TEST_EN)
UART_CTS: P1.34(UART_CTS(1.8V)) P2.34(UART_CTS)
UART_RTS: P1.36(UART_RTS(1.8V)) P2.36(UART_RTS)
UART_RX: P1.22(UART_RX(1.8V)) P2.22(UART_RX)
UART_TX: P1.32(UART_TX(1.8V)) P2.32(UART_TX)
UART_WAKE#: P1.20(UART_WAKE#) P2.20(UART_WAKE#)
USB2_DN: P1.5(USB_D-) P2.5(USB_D-)
USB2_DP: P1.3(USB_D+) P2.3(USB_D+)
VDC_IN: D5.CATHODE J1.1 J1.3
VPORTP: C37.1 C38.1 C39.1 C50.2 C51.2 D1.2(OUT_P) D2.CATHODE D4.2(OUT_P) R29.1 R31.1 U3.1(VDD) U4.2(VIN)
WIFI_RST#: P2.52(PERST0#) R22.1
WIFI_SUSCLK: P1.50(SUSCLK) P2.50(SUSCLK)
XTAL1_LAN0: C29.2 U2.46(XTAL1_/_ATESTN)
N4797410: R127.2 U2.1(LAN_PWR_GD_/_AVDD3p3)

Not connected (* = marked no-connect by the designer): P1 6(LED1#)* 9(SDIO_CLK)* 11(SDIO_CMD)* 13(SDIO_D0)* 15(SDIO_D1)* 16(LED2#)* 17(SDIO_D2)* 19(SDIO_D3)* 21(SDIO_WAKE#)* 23(SDIO_RESET#)* 38(RSVD/CLINK_RST)* 40(RSVD/CLINK_DATA)* 42(RSVD/CLINK_CLK)* 44(COEX3(1.8V))* 46(COEX2_RXD(1.8V))* 48(COEX1_TXD(1.8V))* 64(RSVD)* 66(UIM_SWP/RESET1#)*; P2 6(LED1#)* 9(SDIO_CLK)* 11(SDIO_CMD)* 13(SDIO_D0)* 15(SDIO_D1)* 16(LED2#)* 17(SDIO_D2)* 19(SDIO_D3)* 21(SDIO_WAKE#)* 23(SDIO_RESET#)* 38(RSVD/CLINK_RST)* 40(RSVD/CLINK_DATA)* 44(COEX3(1.8V))* 46(COEX2(1.8V))* 48(COEX1(1.8V))* 59(RSVD/PETP1)* 61(RSVD/PETN1)* 64(UART_RTS(1.8V))* 65(RSVD/PERP1)* 67(RSVD/PERN1)* 68(UIM_PWRSNK/CLKREQ1#)* 70(UIM_PWRSRC/PEWAKE1#)* 71(RSVD/REFCLKP1)* 73(RSVD/REFCLKN1)*; P5 5(PERN3)* 6(NC)* 7(PERP3)* 8(NC)* 10(DAS/DSS#)* 11(PETN3)* 13(PETP3)* 17(PERN2)* 19(PERP2)* 23(PETN2)* 25(PETP2)* 29(PERN1)* 31(PERP1)* 35(PETN1)* 36(NC)* 37(PETP1)* 52(CLKREQ*/NC)* 53(REFCLKN)* 54(PEWAKE*/NC)* 55(REFCLKP)* 67(NC)*; P6 5(PERN3)* 6(NC)* 7(PERP3)* 8(NC)* 10(DAS/DSS#)* 11(PETN3)* 13(PETP3)* 17(PERN2)* 19(PERP2)* 23(PETN2)* 25(PETP2)* 29(PERN1)* 31(PERP1)* 35(PETN1)* 36(NC)* 37(PETP1)* 52(CLKREQ*/NC)* 53(REFCLKN)* 54(PEWAKE*/NC)* 55(REFCLKP)* 67(NC)*; RN16 1(RA1)*; U1 7(WP)*; U2 12(RSVD12_PU_/__NVM_SI)* 13(RSVD13_PU_/_NVM_SK)* 14(RSVD14_PU_/__NVM_SO)* 15(RSVD15_PU_/_NVM_CS_N)* 22(NC_/_AVDD1p9)* 34(RSVD34_PU)* 35(RSVD35_PU)* 36(RSVD36_PU)* 43(RSVD43_/_XTAL1)* 44(RSVD44_/__AVDD19)* 45(XTAL2_/_ATEST_P)* 60(SDP3_/_VDD1p0)* 61(SDP1[PCIe_DIS]__/_AVDD1p9)* 62(SDP2_/_CTRL10)* 63(SDP0_/_AVDD1p9)*; U3 14(NC)* 15(NC)* 17(TPL)* 18(TPH)* 19(~{BT})* 20(NC)*

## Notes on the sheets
sheet 1
- FC-POED Rev 1.1
- Revision notes
- V1.1:
  1. Separate the 3.3V_A and 3.3V_S rails
  2. Add eMMC RST and eMMC_STROBE resistors
- Revision EEPROM
- CP
- CP
- DNP
- DNP
- CP
- DNP
- SMB:A8h-A9h
- 1010 100x
- Change the component to 111S30801S
sheet 2
- PCB EDGE CONN PADS (M.2 Key E)
- M.2 Key E, WiFi & BT
- DNP
- 4K PU on base board
- PCIE 3
- 2230
- M.2 WiFi
- Pin 58, 60, 62, 64
  Those pins were dedicated for I2C in M.2 1.0
  but actually not used in StP.
  In new M.2 for 2015 it is used, serves as  ISH UART,
  and its voltage level is 1.8 V
  ISH functionality can be used for future advanced capabilities
  of low power operation.
sheet 3
- PCI Clock
- The PCI clock enable.
- NP
- 100K PU on the base board
sheet 4
- SECONDARY CoM/SoM ETHERNET RJ45 PoE
- PoE RECT
- PoE Magnetcs
- up to 58V
- From PSE
- up to 58V
- From PSE AUX
- up to 58V
- Connect R?
  GND for 12.5% Duty Cycle
  NC for 26.4% Duty Cycle
- NOP
- NOP
- NOP
- REV 1.1
- REV 1.1
- e.g. for 12V
  from POE
  custom M.2
- 3.32V max
- PoE Vin to 12V@3.5A
- @0.5A
- Vin up to 60V
- Internal PU
- max 8V, 1.2V EN
- 27uH-47uH @5.5A
- H=5mm
- Vout=0.8V/10K*(140K+10K)=12V@1.25A
- RT
- ~400KHz
- 0.8V
- 100V @12A
- 147K
- 0.8V
- Softstart
  = 1.02ms
- 10.5K
sheet 5
- PCB EDGE CONN PADS (M.2 Key M)
- M.2 Key M SATA
- RN's are on SBC-APL
- RN's are on SBC-APL
- OUTPUT FLAG
  GND = SATA
- OUTPUT FLAG
  GND = SATA
- NOT CONNECTED ON BASE
- NOT CONNECTED ON BASE
- 2280
- M.2 SATA
- Plated hole for 2260
  Drill 4.0mm
  Plated 5.0mm
